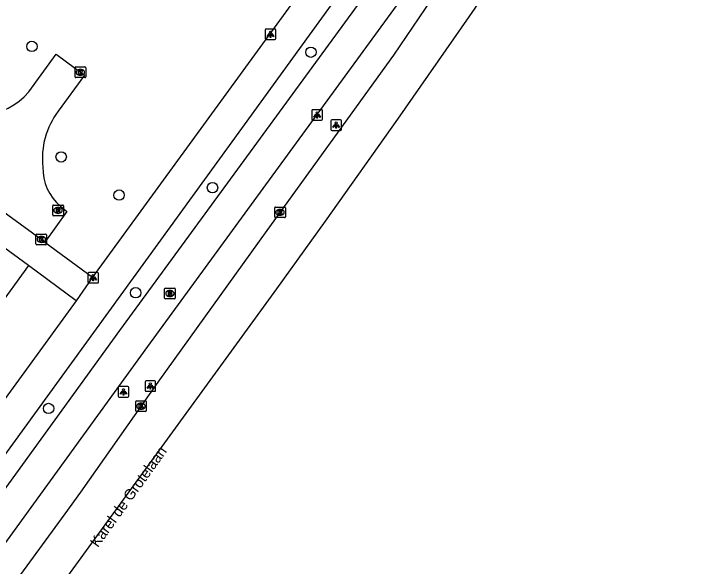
# Model space of a CAD drawing. Extents: x 159675 to 160530, y 382179 to 382901.
# Drawn here: x 160339.1 to 160404.8, y 382521.1 to 382573 of the extents above; entities that cross this region are included whole.
import ezdxf

# ---------------------------------------------------------------- set-up
doc = ezdxf.new("R2010")
doc.units = 0
for name, color, linetype in [('IMGEO_Boom', 7, 'Continuous'), ('IMGEO_Fietspad_gesloten', 7, 'Continuous'), ('IMGEO_Kolk', 7, 'Continuous'), ('IMGEO_Lichtpunt', 7, 'Continuous'), ('IMGEO_Openbare_ruimte_label', 7, 'Continuous'), ('IMGEO_Pand', 7, 'Continuous'), ('IMGEO_Rijbaan_lokaal_gesloten', 7, 'Continuous'), ('IMGEO_Rijbaan_lokaal_open', 7, 'Continuous'), ('IMGEO_Rioolput', 7, 'Continuous'), ('IMGEO_Voetpad_open', 7, 'Continuous')]:
    doc.layers.add(name, color=color, linetype=linetype)

msp = doc.modelspace()

# ---------------------------------------------------------------- linework, layer by layer
at = {"layer": 'IMGEO_Boom'}
for centre in [(160340.769, 382569.979), (160367.041, 382569.435), (160343.525, 382559.584), (160357.77, 382556.689), (160348.972, 382555.988), (160350.538, 382546.804), (160342.338, 382535.914)]:
    msp.add_circle(centre, 0.489, dxfattribs=at)
at = {"layer": 'IMGEO_Fietspad_gesloten'}
for points in [[(160398.827, 382611.342), (160349.002, 382543.246), (160311.53, 382491.554), (160266.645, 382429.855), (160257.187, 382416.772)], [(160401.131, 382609.485), (160351.662, 382541.731), (160259.615, 382414.865)]]:
    msp.add_lwpolyline(points, dxfattribs=at)
at = {"layer": 'IMGEO_Kolk'}
for p, q in [((160344.83, 382567.118), (160344.83, 382567.97)), ((160344.905, 382568.044), (160345.757, 382568.044)), ((160345.318, 382567.824), (160345.343, 382567.824)), ((160345.831, 382567.97), (160345.831, 382567.118)), ((160345.757, 382567.044), (160344.905, 382567.044)), ((160345.341, 382567.264), (160345.316, 382567.264)), ((160363.632, 382553.943), (160363.632, 382554.795)), ((160363.707, 382554.869), (160364.559, 382554.869)), ((160364.12, 382554.649), (160364.145, 382554.649)), ((160364.633, 382554.795), (160364.633, 382553.943)), ((160364.559, 382553.869), (160363.707, 382553.869)), ((160364.143, 382554.089), (160364.118, 382554.089)), ((160341.152, 382551.393), (160341.152, 382552.245)), ((160341.227, 382552.319), (160342.079, 382552.319)), ((160341.64, 382552.099), (160341.665, 382552.099)), ((160342.153, 382552.245), (160342.153, 382551.393)), ((160342.079, 382551.319), (160341.227, 382551.319)), ((160341.663, 382551.539), (160341.638, 382551.539)), ((160350.54, 382535.703), (160350.54, 382536.555)), ((160350.615, 382536.629), (160351.467, 382536.629)), ((160351.028, 382536.409), (160351.053, 382536.409)), ((160351.541, 382536.555), (160351.541, 382535.703)), ((160351.467, 382535.629), (160350.615, 382535.629)), ((160351.051, 382535.849), (160351.026, 382535.849))]:
    msp.add_line(p, q, dxfattribs=at)
for points in [[(160344.83, 382567.118), (160344.83, 382567.97)], [(160344.905, 382568.044), (160345.757, 382568.044)], [(160345.151, 382567.744), (160345.274, 382567.744), (160345.274, 382567.593), (160345.404, 382567.744), (160345.568, 382567.744), (160345.422, 382567.593), (160345.575, 382567.344), (160345.423, 382567.344), (160345.338, 382567.508), (160345.274, 382567.441), (160345.274, 382567.344), (160345.151, 382567.344), (160345.151, 382567.744)], [(160345.831, 382567.97), (160345.831, 382567.118)], [(160345.757, 382567.044), (160344.905, 382567.044)], [(160363.632, 382553.943), (160363.632, 382554.795)], [(160363.707, 382554.869), (160364.559, 382554.869)], [(160363.953, 382554.569), (160364.076, 382554.569), (160364.076, 382554.418), (160364.206, 382554.569), (160364.37, 382554.569), (160364.224, 382554.418), (160364.377, 382554.169), (160364.225, 382554.169), (160364.14, 382554.333), (160364.076, 382554.266), (160364.076, 382554.169), (160363.953, 382554.169), (160363.953, 382554.569)], [(160364.633, 382554.795), (160364.633, 382553.943)], [(160364.559, 382553.869), (160363.707, 382553.869)], [(160341.152, 382551.393), (160341.152, 382552.245)], [(160341.227, 382552.319), (160342.079, 382552.319)], [(160341.473, 382552.019), (160341.596, 382552.019), (160341.596, 382551.868), (160341.726, 382552.019), (160341.89, 382552.019), (160341.744, 382551.868), (160341.897, 382551.619), (160341.745, 382551.619), (160341.66, 382551.783), (160341.596, 382551.716), (160341.596, 382551.619), (160341.473, 382551.619), (160341.473, 382552.019)], [(160342.153, 382552.245), (160342.153, 382551.393)], [(160342.079, 382551.319), (160341.227, 382551.319)], [(160350.54, 382535.703), (160350.54, 382536.555)], [(160350.615, 382536.629), (160351.467, 382536.629)], [(160350.861, 382536.329), (160350.984, 382536.329), (160350.984, 382536.178), (160351.114, 382536.329), (160351.278, 382536.329), (160351.132, 382536.178), (160351.285, 382535.929), (160351.133, 382535.929), (160351.048, 382536.093), (160350.984, 382536.026), (160350.984, 382535.929), (160350.861, 382535.929), (160350.861, 382536.329)], [(160351.541, 382536.555), (160351.541, 382535.703)], [(160351.467, 382535.629), (160350.615, 382535.629)]]:
    msp.add_lwpolyline(points, dxfattribs=at)
for centre, start, end in [((160344.907, 382567.968), 91.55205, 178.44795), ((160344.907, 382567.968), 91.55205, 178.44795), ((160345.755, 382567.968), 1.55205, 88.44795), ((160345.755, 382567.968), 1.55205, 88.44795), ((160344.907, 382567.12), 181.55205, 268.44795), ((160344.907, 382567.12), 181.55205, 268.44795), ((160345.755, 382567.12), 271.55205, 358.44795), ((160345.755, 382567.12), 271.55205, 358.44795), ((160363.709, 382554.793), 91.55205, 178.44795), ((160363.709, 382554.793), 91.55205, 178.44795), ((160364.557, 382554.793), 1.55205, 88.44795), ((160364.557, 382554.793), 1.55205, 88.44795), ((160363.709, 382553.945), 181.55205, 268.44795), ((160363.709, 382553.945), 181.55205, 268.44795), ((160364.557, 382553.945), 271.55205, 358.44795), ((160364.557, 382553.945), 271.55205, 358.44795), ((160341.229, 382552.243), 91.55205, 178.44795), ((160341.229, 382552.243), 91.55205, 178.44795), ((160342.077, 382552.243), 1.55205, 88.44795), ((160342.077, 382552.243), 1.55205, 88.44795), ((160341.229, 382551.395), 181.55205, 268.44795), ((160341.229, 382551.395), 181.55205, 268.44795), ((160342.077, 382551.395), 271.55205, 358.44795), ((160342.077, 382551.395), 271.55205, 358.44795), ((160350.617, 382536.553), 91.55205, 178.44795), ((160350.617, 382536.553), 91.55205, 178.44795), ((160351.465, 382536.553), 1.55205, 88.44795), ((160351.465, 382536.553), 1.55205, 88.44795), ((160350.617, 382535.705), 181.55205, 268.44795), ((160350.617, 382535.705), 181.55205, 268.44795), ((160351.465, 382535.705), 271.55205, 358.44795), ((160351.465, 382535.705), 271.55205, 358.44795)]:
    msp.add_arc(centre, 0.0765, start, end, dxfattribs=at)
for centre, major_axis, ratio, start_param, end_param in [((160345.317, 382567.544), (-0.387, 0.002), 0.722429, 4.712389, 7.853982), ((160345.342, 382567.544), (-0.39, 0.002), 0.717154, 1.570796, 4.712389), ((160364.119, 382554.369), (-0.387, 0.002), 0.722429, 4.712389, 7.853982), ((160364.144, 382554.369), (-0.39, 0.002), 0.717154, 1.570796, 4.712389), ((160341.639, 382551.819), (-0.387, 0.002), 0.722429, 4.712389, 7.853982), ((160341.664, 382551.819), (-0.39, 0.002), 0.717154, 1.570796, 4.712389), ((160351.027, 382536.129), (-0.387, 0.002), 0.722429, 4.712389, 7.853982), ((160351.052, 382536.129), (-0.39, 0.002), 0.717154, 1.570796, 4.712389)]:
    msp.add_ellipse(centre, major_axis=major_axis, ratio=ratio, start_param=start_param, end_param=end_param, dxfattribs=at)
at = {"layer": 'IMGEO_Lichtpunt'}
for p, q in [((160362.727, 382571.522), (160362.727, 382570.715)), ((160362.727, 382571.522), (160362.727, 382570.715)), ((160363.629, 382571.617), (160362.821, 382571.617)), ((160363.629, 382571.617), (160362.821, 382571.617)), ((160363.723, 382570.715), (160363.723, 382571.522)), ((160363.723, 382570.715), (160363.723, 382571.522)), ((160362.821, 382570.621), (160363.629, 382570.621)), ((160362.821, 382570.621), (160363.629, 382570.621)), ((160367.135, 382563.932), (160367.135, 382563.125)), ((160367.135, 382563.932), (160367.135, 382563.125)), ((160368.037, 382564.027), (160367.229, 382564.027)), ((160368.037, 382564.027), (160367.229, 382564.027)), ((160368.131, 382563.125), (160368.131, 382563.932)), ((160368.131, 382563.125), (160368.131, 382563.932)), ((160367.229, 382563.031), (160368.037, 382563.031)), ((160367.229, 382563.031), (160368.037, 382563.031)), ((160368.92, 382562.979), (160368.92, 382562.172)), ((160368.92, 382562.979), (160368.92, 382562.172)), ((160369.822, 382563.074), (160369.014, 382563.074)), ((160369.822, 382563.074), (160369.014, 382563.074)), ((160369.916, 382562.172), (160369.916, 382562.979)), ((160369.916, 382562.172), (160369.916, 382562.979)), ((160369.014, 382562.078), (160369.822, 382562.078)), ((160369.014, 382562.078), (160369.822, 382562.078)), ((160346.038, 382548.621), (160346.038, 382547.814)), ((160346.038, 382548.621), (160346.038, 382547.814)), ((160346.94, 382548.716), (160346.132, 382548.716)), ((160346.94, 382548.716), (160346.132, 382548.716)), ((160347.034, 382547.814), (160347.034, 382548.621)), ((160347.034, 382547.814), (160347.034, 382548.621)), ((160346.132, 382547.72), (160346.94, 382547.72)), ((160346.132, 382547.72), (160346.94, 382547.72)), ((160349.788, 382537.974), (160348.98, 382537.974)), ((160349.788, 382537.974), (160348.98, 382537.974)), ((160351.423, 382538.429), (160351.423, 382537.622)), ((160351.423, 382538.429), (160351.423, 382537.622)), ((160352.325, 382538.524), (160351.517, 382538.524)), ((160352.325, 382538.524), (160351.517, 382538.524)), ((160352.419, 382537.622), (160352.419, 382538.429)), ((160352.419, 382537.622), (160352.419, 382538.429)), ((160348.886, 382537.879), (160348.886, 382537.072)), ((160348.886, 382537.879), (160348.886, 382537.072)), ((160349.882, 382537.072), (160349.882, 382537.879)), ((160349.882, 382537.072), (160349.882, 382537.879)), ((160351.517, 382537.528), (160352.325, 382537.528)), ((160351.517, 382537.528), (160352.325, 382537.528)), ((160348.98, 382536.978), (160349.788, 382536.978)), ((160348.98, 382536.978), (160349.788, 382536.978))]:
    msp.add_line(p, q, dxfattribs=at)
for points in [[(160363.101, 382571.186), (160363.14, 382571.158), (160362.952, 382570.896), (160362.914, 382570.923), (160363.101, 382571.186)], [(160363.203, 382571.138), (160363.25, 382571.138), (160363.25, 382570.816), (160363.203, 382570.816), (160363.203, 382571.138)], [(160363.313, 382571.158), (160363.351, 382571.185), (160363.538, 382570.923), (160363.499, 382570.895), (160363.313, 382571.158)], [(160367.509, 382563.596), (160367.548, 382563.568), (160367.36, 382563.306), (160367.322, 382563.333), (160367.509, 382563.596)], [(160367.611, 382563.548), (160367.658, 382563.548), (160367.658, 382563.226), (160367.611, 382563.226), (160367.611, 382563.548)], [(160367.721, 382563.568), (160367.759, 382563.595), (160367.946, 382563.333), (160367.907, 382563.305), (160367.721, 382563.568)], [(160369.294, 382562.643), (160369.333, 382562.615), (160369.145, 382562.353), (160369.107, 382562.38), (160369.294, 382562.643)], [(160369.396, 382562.595), (160369.443, 382562.595), (160369.443, 382562.273), (160369.396, 382562.273), (160369.396, 382562.595)], [(160369.506, 382562.615), (160369.544, 382562.642), (160369.731, 382562.38), (160369.692, 382562.352), (160369.506, 382562.615)], [(160346.412, 382548.285), (160346.451, 382548.257), (160346.263, 382547.995), (160346.225, 382548.022), (160346.412, 382548.285)], [(160346.514, 382548.237), (160346.561, 382548.237), (160346.561, 382547.915), (160346.514, 382547.915), (160346.514, 382548.237)], [(160346.624, 382548.257), (160346.662, 382548.284), (160346.849, 382548.022), (160346.81, 382547.994), (160346.624, 382548.257)], [(160351.797, 382538.093), (160351.836, 382538.065), (160351.648, 382537.803), (160351.61, 382537.83), (160351.797, 382538.093)], [(160351.899, 382538.045), (160351.946, 382538.045), (160351.946, 382537.723), (160351.899, 382537.723), (160351.899, 382538.045)], [(160352.009, 382538.065), (160352.047, 382538.092), (160352.234, 382537.83), (160352.195, 382537.802), (160352.009, 382538.065)], [(160349.26, 382537.543), (160349.299, 382537.515), (160349.111, 382537.253), (160349.073, 382537.28), (160349.26, 382537.543)], [(160349.362, 382537.495), (160349.409, 382537.495), (160349.409, 382537.173), (160349.362, 382537.173), (160349.362, 382537.495)], [(160349.472, 382537.515), (160349.51, 382537.542), (160349.697, 382537.28), (160349.658, 382537.252), (160349.472, 382537.515)]]:
    msp.add_lwpolyline(points, dxfattribs=at)
for centre in [(160363.226, 382571.32), (160367.634, 382563.73), (160369.419, 382562.777), (160346.537, 382548.419), (160351.922, 382538.227), (160349.385, 382537.677)]:
    msp.add_circle(centre, 0.0994, dxfattribs=at)
for centre, start, end in [((160362.821, 382571.522), 90, 180), ((160362.821, 382571.522), 90, 180), ((160363.629, 382571.522), 0, 90), ((160363.629, 382571.522), 0, 90), ((160362.821, 382570.715), 180, 270), ((160362.821, 382570.715), 180, 270), ((160363.629, 382570.715), 270, 0), ((160363.629, 382570.715), 270, 360), ((160367.229, 382563.932), 90, 180), ((160367.229, 382563.932), 90, 180), ((160368.037, 382563.932), 0, 90), ((160368.037, 382563.932), 0, 90), ((160367.229, 382563.125), 180, 270), ((160367.229, 382563.125), 180, 270), ((160368.037, 382563.125), 270, 0), ((160368.037, 382563.125), 270, 360), ((160369.014, 382562.979), 90, 180), ((160369.014, 382562.979), 90, 180), ((160369.822, 382562.979), 0, 90), ((160369.822, 382562.979), 0, 90), ((160369.014, 382562.172), 180, 270), ((160369.014, 382562.172), 180, 270), ((160369.822, 382562.172), 270, 0), ((160369.822, 382562.172), 270, 360), ((160346.132, 382548.621), 90, 180), ((160346.132, 382548.621), 90, 180), ((160346.94, 382548.621), 0, 90), ((160346.94, 382548.621), 0, 90), ((160346.132, 382547.814), 180, 270), ((160346.132, 382547.814), 180, 270), ((160346.94, 382547.814), 270, 0), ((160346.94, 382547.814), 270, 360), ((160348.98, 382537.879), 90, 180), ((160348.98, 382537.879), 90, 180), ((160349.788, 382537.879), 0, 90), ((160349.788, 382537.879), 0, 90), ((160351.517, 382538.429), 90, 180), ((160351.517, 382538.429), 90, 180), ((160352.325, 382538.429), 0, 90), ((160352.325, 382538.429), 0, 90), ((160351.517, 382537.622), 180, 270), ((160351.517, 382537.622), 180, 270), ((160352.325, 382537.622), 270, 0), ((160352.325, 382537.622), 270, 360), ((160348.98, 382537.072), 180, 270), ((160348.98, 382537.072), 180, 270), ((160349.788, 382537.072), 270, 0), ((160349.788, 382537.072), 270, 360)]:
    msp.add_arc(centre, 0.0946, start, end, dxfattribs=at)
at = {"layer": 'IMGEO_Pand'}
for points in [[(160340.442, 382549.369), (160334.533, 382553.667)], [(160340.442, 382549.369), (160334.331, 382540.968), (160330.288, 382543.909), (160320.097, 382551.321)]]:
    msp.add_lwpolyline(points, dxfattribs=at)
at = {"layer": 'IMGEO_Rijbaan_lokaal_gesloten'}
for points in [[(160401.931, 382608.929), (160390.705, 382592.122), (160378.396, 382574.452), (160374.83, 382569.169), (160362.897, 382552.659), (160352.635, 382538.399), (160345.353, 382528.03), (160343.873, 382526.012), (160324.815, 382500), (160297.701, 382462.662), (160291.094, 382453.563), (160260.653, 382414.245)], [(160404.808, 382606.478), (160403.96, 382605.241), (160392.452, 382588.267), (160386.34, 382579.205), (160381.894, 382572.757), (160375.19, 382563.12), (160368.394, 382553.547), (160363.785, 382547.168), (160338.352, 382512.2), (160312.946, 382477.26), (160301.422, 382461.465), (160294.406, 382451.971), (160280.167, 382433.302), (160272.383, 382423.339), (160263.586, 382412.092)]]:
    msp.add_lwpolyline(points, dxfattribs=at)
at = {"layer": 'IMGEO_Rijbaan_lokaal_open'}
for points in [[(160341.99, 382551.571), (160313.617, 382572.218)], [(160340.489, 382565.698), (160343.047, 382569.265), (160345.707, 382567.262), (160343.23, 382563.874)], [(160343.467, 382554.933), (160344.044, 382554.45), (160341.99, 382551.571)]]:
    msp.add_lwpolyline(points, dxfattribs=at)
for centre, radius, start, end in [((160335.641, 382569.925), 6.432, 231.35073, 318.91108), ((160349.2, 382559.422), 7.447, 143.28752, 186.0987), ((160346.503, 382558.533), 4.709, 178.8031, 229.8558)]:
    msp.add_arc(centre, radius, start, end, dxfattribs=at)
at = {"layer": 'IMGEO_Rioolput'}
for p, q in [((160342.73, 382554.124), (160342.73, 382554.976)), ((160342.805, 382555.05), (160343.657, 382555.05)), ((160343.218, 382554.83), (160343.243, 382554.83)), ((160343.731, 382554.976), (160343.731, 382554.124)), ((160343.657, 382554.05), (160342.805, 382554.05)), ((160343.241, 382554.27), (160343.216, 382554.27)), ((160353.338, 382547.231), (160354.19, 382547.231)), ((160353.263, 382546.305), (160353.263, 382547.157)), ((160353.751, 382547.011), (160353.776, 382547.011)), ((160354.264, 382547.157), (160354.264, 382546.305)), ((160354.19, 382546.231), (160353.338, 382546.231)), ((160353.774, 382546.451), (160353.749, 382546.451))]:
    msp.add_line(p, q, dxfattribs=at)
for points in [[(160342.73, 382554.124), (160342.73, 382554.976)], [(160342.805, 382555.05), (160343.657, 382555.05)], [(160343.319, 382554.748), (160343.067, 382554.75), (160343.067, 382554.35)], [(160343.067, 382554.35), (160343.191, 382554.35), (160343.191, 382554.512), (160343.202, 382554.512)], [(160343.245, 382554.669), (160343.191, 382554.669), (160343.191, 382554.588)], [(160343.191, 382554.588), (160343.243, 382554.588)], [(160343.249, 382554.483), (160343.32, 382554.35), (160343.46, 382554.35), (160343.395, 382554.476)], [(160343.731, 382554.976), (160343.731, 382554.124)], [(160343.657, 382554.05), (160342.805, 382554.05)], [(160353.338, 382547.231), (160354.19, 382547.231)], [(160353.263, 382546.305), (160353.263, 382547.157)], [(160353.852, 382546.929), (160353.6, 382546.931), (160353.6, 382546.531)], [(160353.6, 382546.531), (160353.724, 382546.531), (160353.724, 382546.693), (160353.735, 382546.693)], [(160353.778, 382546.85), (160353.724, 382546.85), (160353.724, 382546.769)], [(160353.724, 382546.769), (160353.776, 382546.769)], [(160353.782, 382546.664), (160353.853, 382546.531), (160353.993, 382546.531), (160353.928, 382546.657)], [(160354.264, 382547.157), (160354.264, 382546.305)], [(160354.19, 382546.231), (160353.338, 382546.231)]]:
    msp.add_lwpolyline(points, dxfattribs=at)
for centre, radius, start, end in [((160342.807, 382554.974), 0.0765, 91.55205, 178.44795), ((160342.807, 382554.974), 0.0765, 91.55205, 178.44795), ((160343.201, 382554.459), 0.0533, 26.02933, 88.69889), ((160343.227, 382554.777), 0.19, 274.7715, 282.96867), ((160343.251, 382554.573), 0.0964, 77.00612, 93.18647), ((160343.265, 382554.63), 0.0378, 276.66336, 79.67722), ((160343.318, 382554.638), 0.109, 350.36119, 89.41601), ((160343.316, 382554.638), 0.112, 277.58423, 350.98172), ((160343.3, 382554.423), 0.108, 29.51342, 73.79051), ((160343.655, 382554.974), 0.0765, 1.55205, 88.44795), ((160343.655, 382554.974), 0.0765, 1.55205, 88.44795), ((160342.807, 382554.126), 0.0765, 181.55205, 268.44795), ((160342.807, 382554.126), 0.0765, 181.55205, 268.44795), ((160343.655, 382554.126), 0.0765, 271.55205, 358.44795), ((160343.655, 382554.126), 0.0765, 271.55205, 358.44795), ((160353.34, 382547.155), 0.0765, 91.55205, 178.44795), ((160353.34, 382547.155), 0.0765, 91.55205, 178.44795), ((160354.188, 382547.155), 0.0765, 1.55205, 88.44795), ((160354.188, 382547.155), 0.0765, 1.55205, 88.44795), ((160353.734, 382546.64), 0.0533, 26.02933, 88.69889), ((160353.76, 382546.958), 0.19, 274.7715, 282.96867), ((160353.784, 382546.754), 0.0964, 77.00612, 93.18647), ((160353.798, 382546.811), 0.0378, 276.66336, 79.67722), ((160353.851, 382546.819), 0.109, 350.36119, 89.41601), ((160353.849, 382546.819), 0.112, 277.58423, 350.98172), ((160353.833, 382546.604), 0.108, 29.51342, 73.79051), ((160353.34, 382546.307), 0.0765, 181.55205, 268.44795), ((160353.34, 382546.307), 0.0765, 181.55205, 268.44795), ((160354.188, 382546.307), 0.0765, 271.55205, 358.44795), ((160354.188, 382546.307), 0.0765, 271.55205, 358.44795)]:
    msp.add_arc(centre, radius, start, end, dxfattribs=at)
for centre, major_axis, ratio, start_param, end_param in [((160343.217, 382554.55), (-0.387, 0.002), 0.722429, 4.712389, 7.853982), ((160343.242, 382554.55), (-0.39, 0.002), 0.717154, 1.570796, 4.712389), ((160353.75, 382546.731), (-0.387, 0.002), 0.722429, 4.712389, 7.853982), ((160353.775, 382546.731), (-0.39, 0.002), 0.717154, 1.570796, 4.712389)]:
    msp.add_ellipse(centre, major_axis=major_axis, ratio=ratio, start_param=start_param, end_param=end_param, dxfattribs=at)
at = {"layer": 'IMGEO_Voetpad_open'}
for points in [[(160399.135, 382620.521), (160346.474, 382548.259)], [(160257.187, 382416.772), (160255.648, 382417.937), (160291.256, 382466.928), (160315.294, 382500), (160346.84, 382543.397), (160360.539, 382562.246), (160397.047, 382612.59), (160398.73, 382611.41), (160398.827, 382611.342)], [(160341.99, 382551.571), (160346.474, 382548.259)], [(160344.923, 382546.056), (160340.442, 382549.369)], [(160346.474, 382548.259), (160344.923, 382546.056)], [(160344.923, 382546.056), (160311.42, 382500), (160295.603, 382478.257)]]:
    msp.add_lwpolyline(points, dxfattribs=at)

# ---------------------------------------------------------------- texts
at = {"layer": 'IMGEO_Openbare_ruimte_label'}
msp.add_text('Karel de Grotelaan', height=1, rotation=54.3224, dxfattribs=at).set_placement((160346.98, 382522.773))

doc.saveas('drawing.dxf')
